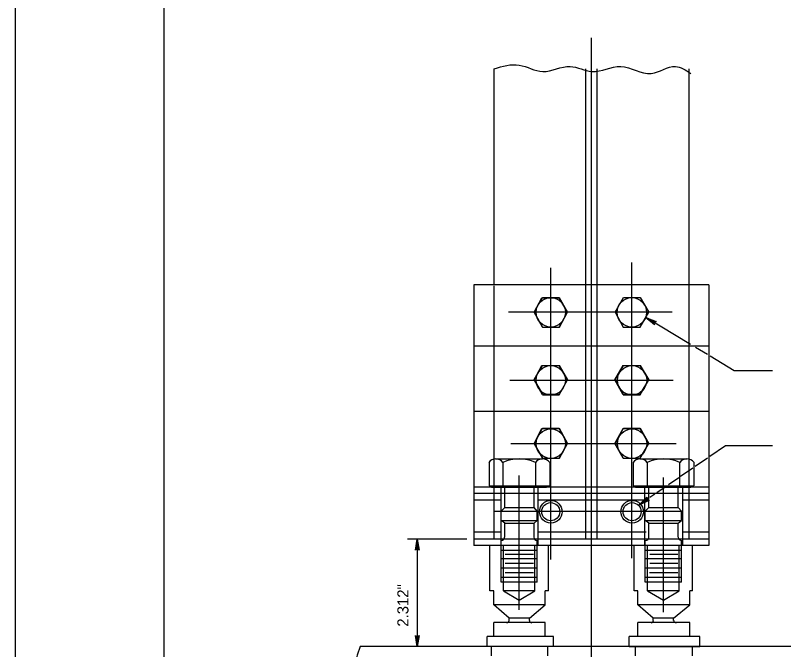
# Model space of a CAD drawing. Extents: x 637580 to 641008, y 294594 to 295782.
# Drawn here: x 637580.3 to 637787.5, y 294775.6 to 294946.5 of the extents above; entities that cross this region are included whole.
import ezdxf

# ---------------------------------------------------------------- set-up
doc = ezdxf.new("R2010")
doc.units = 0
for name, color, linetype in [('1', 7, 'Continuous'), ('2', 7, 'Continuous'), ('3', 7, 'Continuous'), ('PLT-BNDY', 7, 'Continuous')]:
    doc.layers.add(name, color=color, linetype=linetype)

# ---------------------------------------------------------------- blocks, each defined once
blk = doc.blocks.new('RARROW')
at = {"layer": '3'}
blk.add_lwpolyline([(-2.2695, 0.285), (-2.184875, 0.12075), (0, 0), (-2.2695, 0.285), (-2.38575, 0.384625), (0, 0), (-2.183125, -0.108), (-2.262875, -0.2705), (0, 0), (-2.38575, -0.379125), (-2.262875, -0.2705)], dxfattribs=at)

msp = doc.modelspace()

# ---------------------------------------------------------------- linework, layer by layer
at = {"layer": '1'}
msp.add_line((637620.31, 295172.63), (637620.31, 294608.63), dxfattribs=at)
at = {"layer": '2'}
for p, q in [((637735.69, 294688.38), (637735.69, 294940.5)), ((637709.44, 294873.88), (637709.44, 294932.13)), ((637734.19, 294805.38), (637734.19, 294932.13)), ((637737.19, 294805.38), (637737.19, 294932.13)), ((637762.06, 294873.63), (637762.06, 294932.13)), ((637746.56, 294800.25), (637746.56, 294879.88)), ((637724.69, 294799.88), (637724.69, 294878.5)), ((637767.31, 294873.88), (637703.94, 294873.88)), ((637703.94, 294873.88), (637703.94, 294805.38)), ((637709.44, 294805.38), (637709.44, 294873.63)), ((637762.06, 294857.96), (637762.06, 294873.63)), ((637767.31, 294873.88), (637767.31, 294805.38)), ((637720.19, 294866.5), (637722.44, 294870.5)), ((637720.19, 294866.5), (637722.31, 294870.38)), ((637722.31, 294870.38), (637726.94, 294870.38)), ((637722.44, 294870.5), (637726.94, 294870.5)), ((637726.94, 294870.5), (637729.19, 294866.5)), ((637729.19, 294866.5), (637726.94, 294870.38)), ((637742.06, 294866.5), (637744.31, 294870.5)), ((637744.31, 294870.5), (637748.81, 294870.5)), ((637748.81, 294870.5), (637751.19, 294866.5)), ((637757.44, 294866.5), (637713.31, 294866.5)), ((637720.19, 294866.5), (637722.44, 294862.5)), ((637722.44, 294862.5), (637720.19, 294866.5)), ((637724.69, 294866.5), (637724.69, 294866.5)), ((637724.69, 294866.5), (637724.69, 294866.5)), ((637724.69, 294866.5), (637724.69, 294866.5)), ((637726.94, 294862.5), (637729.19, 294866.5)), ((637727.06, 294862.5), (637729.19, 294866.5)), ((637742.06, 294866.5), (637744.19, 294862.5)), ((637746.56, 294866.5), (637746.56, 294866.5)), ((637746.56, 294866.5), (637746.56, 294866.5)), ((637746.56, 294866.5), (637746.56, 294866.5)), ((637748.81, 294862.5), (637751.19, 294866.5)), ((637748.81, 294862.5), (637751.19, 294866.5)), ((637762.39, 294857.83), (637750.33, 294865.06)), ((637722.44, 294862.5), (637727.06, 294862.5)), ((637722.44, 294862.5), (637726.94, 294862.5)), ((637744.19, 294862.5), (637748.81, 294862.5)), ((637767.31, 294857.38), (637703.94, 294857.38)), ((637762.06, 294805.38), (637762.06, 294857.89)), ((637766.96, 294855.09), (637763.72, 294857.03)), ((637774.19, 294850.75), (637767.71, 294854.64)), ((637720.19, 294848.25), (637722.44, 294852.13)), ((637720.19, 294848.25), (637722.31, 294852.13)), ((637722.31, 294852.13), (637726.94, 294852.13)), ((637722.44, 294852.13), (637726.94, 294852.13)), ((637726.94, 294852.13), (637729.19, 294848.25)), ((637729.19, 294848.25), (637726.94, 294852.13)), ((637741.94, 294848.25), (637744.19, 294852.13)), ((637742.06, 294848.25), (637744.31, 294852.13)), ((637744.19, 294852.13), (637748.81, 294852.13)), ((637744.31, 294852.13), (637748.81, 294852.13)), ((637748.81, 294852.13), (637751.19, 294848.25)), ((637751.19, 294848.25), (637748.81, 294852.13)), ((637784.46, 294850.75), (637774.19, 294850.75)), ((637757.69, 294848.13), (637713.69, 294848.13)), ((637720.19, 294848.25), (637722.44, 294844.38)), ((637722.44, 294844.25), (637720.19, 294848.25)), ((637724.69, 294848.13), (637724.69, 294848.13)), ((637724.69, 294848.13), (637724.69, 294848.13)), ((637724.69, 294848.13), (637724.69, 294848.13)), ((637726.94, 294844.25), (637729.19, 294848.25)), ((637727.06, 294844.38), (637729.19, 294848.25)), ((637744.19, 294844.25), (637741.94, 294848.25)), ((637742.06, 294848.25), (637744.19, 294844.38)), ((637746.56, 294848.13), (637746.56, 294848.13)), ((637746.56, 294848.13), (637746.56, 294848.13)), ((637746.56, 294848.13), (637746.56, 294848.13)), ((637748.81, 294844.38), (637751.19, 294848.25)), ((637748.81, 294844.25), (637751.19, 294848.25)), ((637722.44, 294844.38), (637727.06, 294844.38)), ((637722.44, 294844.25), (637726.94, 294844.25)), ((637744.19, 294844.38), (637748.81, 294844.38)), ((637744.19, 294844.25), (637748.81, 294844.25)), ((637767.31, 294839.75), (637703.94, 294839.75)), ((637720.19, 294831), (637722.44, 294835.25)), ((637720.19, 294831.13), (637722.31, 294835.13)), ((637722.31, 294835.13), (637726.94, 294835.13)), ((637722.44, 294835.25), (637726.94, 294835.25)), ((637726.94, 294835.25), (637729.19, 294831.13)), ((637729.19, 294831.13), (637726.94, 294835.13)), ((637741.94, 294831.13), (637744.19, 294835.13)), ((637742.06, 294831), (637744.31, 294835.25)), ((637744.19, 294835.13), (637748.81, 294835.13)), ((637744.31, 294835.25), (637748.81, 294835.25)), ((637748.81, 294835.25), (637751.19, 294831.13)), ((637751.19, 294831.13), (637748.81, 294835.13)), ((637758.56, 294831), (637713.94, 294831)), ((637722.44, 294827.13), (637720.19, 294831.13)), ((637720.19, 294831), (637722.44, 294827.13)), ((637724.69, 294831), (637724.69, 294831)), ((637724.69, 294831), (637724.69, 294831)), ((637724.69, 294831), (637724.69, 294831)), ((637726.94, 294827.13), (637729.19, 294831.13)), ((637727.06, 294827.13), (637729.19, 294831.13)), ((637744.19, 294827.13), (637741.94, 294831.13)), ((637742.06, 294831), (637744.19, 294827.13)), ((637746.56, 294831), (637746.56, 294831)), ((637746.56, 294831), (637746.56, 294831)), ((637746.56, 294831), (637746.56, 294831)), ((637748.81, 294827.13), (637751.19, 294831.13)), ((637748.81, 294827.13), (637751.19, 294831.13)), ((637771.79, 294830.51), (637767.61, 294827.65)), ((637784.46, 294830.51), (637771.79, 294830.51)), ((637708.06, 294826.13), (637708.06, 294826.13)), ((637708.06, 294826.13), (637708.06, 294819.75)), ((637709.81, 294827), (637709.81, 294827)), ((637709.81, 294827), (637711.81, 294827)), ((637711.81, 294827), (637720.56, 294827)), ((637711.81, 294826.13), (637711.81, 294819.75)), ((637711.81, 294826.13), (637711.81, 294826.13)), ((637716.19, 294827), (637716.19, 294827)), ((637720.56, 294827), (637722.44, 294827)), ((637720.56, 294826.13), (637720.56, 294819.75)), ((637720.56, 294826.13), (637720.56, 294826.13)), ((637722.44, 294827.13), (637727.06, 294827.13)), ((637722.44, 294827.13), (637726.94, 294827.13)), ((637722.44, 294827), (637722.44, 294827)), ((637724.44, 294826.13), (637724.44, 294826.13)), ((637724.44, 294826.13), (637724.44, 294819.75)), ((637744.19, 294827.13), (637748.81, 294827.13)), ((637744.19, 294827.13), (637748.81, 294827.13)), ((637746.94, 294826.13), (637746.94, 294826.13)), ((637746.94, 294826.13), (637746.94, 294819.75)), ((637748.69, 294827), (637748.69, 294827)), ((637748.69, 294827), (637750.69, 294827)), ((637750.69, 294827), (637759.44, 294827)), ((637750.69, 294826.13), (637750.69, 294819.75)), ((637750.69, 294826.13), (637750.69, 294826.13)), ((637755.06, 294827), (637755.06, 294827)), ((637759.44, 294827), (637761.44, 294827)), ((637759.44, 294826.13), (637759.44, 294819.75)), ((637759.44, 294826.13), (637759.44, 294826.13)), ((637761.44, 294827), (637761.44, 294827)), ((637763.31, 294826.13), (637763.31, 294826.13)), ((637763.31, 294826.13), (637763.31, 294819.75)), ((637766.98, 294827.21), (637763.65, 294824.94)), ((637763, 294824.48), (637759.65, 294822.19)), ((637716.19, 294786.25), (637716.19, 294822.5)), ((637755.06, 294785.63), (637755.06, 294822)), ((637759.23, 294821.9), (637756.44, 294819.99)), ((637708.06, 294819.75), (637724.44, 294819.75)), ((637708.69, 294819.38), (637708.56, 294819.75)), ((637712.31, 294813.88), (637712.31, 294819.75)), ((637720.19, 294813.88), (637720.19, 294819.75)), ((637723.56, 294819.38), (637723.56, 294819.75)), ((637746.94, 294819.75), (637763.31, 294819.75)), ((637747.56, 294819.38), (637747.44, 294819.75)), ((637751.19, 294813.88), (637751.19, 294819.75)), ((637759.06, 294813.88), (637759.06, 294819.75)), ((637762.44, 294819.38), (637762.56, 294819.75)), ((637711.44, 294819.38), (637703.94, 294819.38)), ((637767.31, 294817.63), (637703.94, 294817.63)), ((637708.69, 294819.38), (637723.56, 294819.38)), ((637711.19, 294819.38), (637711.19, 294803.63)), ((637716.19, 294819.38), (637716.19, 294819.38)), ((637716.19, 294819.38), (637716.19, 294819.38)), ((637721.31, 294803.63), (637721.31, 294819.38)), ((637750.44, 294819.38), (637721.31, 294819.38)), ((637747.56, 294819.38), (637762.44, 294819.38)), ((637749.94, 294819.38), (637749.94, 294803.5)), ((637752.75, 294817.46), (637751.4, 294816.53)), ((637755.24, 294819.16), (637753.29, 294817.83)), ((637755.06, 294819.38), (637755.06, 294819.38)), ((637755.06, 294819.38), (637755.06, 294819.38)), ((637767.31, 294819.38), (637760.19, 294819.38)), ((637760.31, 294803.63), (637760.31, 294819.38)), ((637711.44, 294815.88), (637703.94, 294815.88)), ((637749.94, 294815.88), (637721.31, 294815.88)), ((637751.01, 294816.27), (637748.44, 294814.5)), ((637767.31, 294815.88), (637760.19, 294815.88)), ((637711.31, 294812.88), (637712.31, 294813.88)), ((637712.31, 294813.88), (637720.19, 294813.88)), ((637721.06, 294812.88), (637720.19, 294813.88)), ((637750.19, 294812.88), (637751.19, 294813.88)), ((637751.19, 294813.88), (637759.06, 294813.88)), ((637759.94, 294812.88), (637759.06, 294813.88)), ((637709.31, 294812.88), (637758.06, 294812.88)), ((637711.31, 294812.88), (637721.06, 294812.88)), ((637711.31, 294810.38), (637711.31, 294812.88)), ((637716.19, 294812.88), (637716.19, 294812.88)), ((637721.06, 294810.38), (637721.06, 294812.88)), ((637724.69, 294812.88), (637724.69, 294812.88)), ((637746.56, 294812.88), (637746.56, 294812.88)), ((637750.19, 294812.88), (637759.94, 294812.88)), ((637750.19, 294810.38), (637750.19, 294812.88)), ((637755.06, 294812.88), (637755.06, 294812.88)), ((637759.94, 294810.38), (637759.94, 294812.88)), ((637711.31, 294810.38), (637721.06, 294810.38)), ((637712.31, 294809.63), (637711.31, 294810.38)), ((637712.31, 294805.88), (637712.31, 294809.63)), ((637712.31, 294809.63), (637720.19, 294809.63)), ((637720.19, 294809.63), (637721.06, 294810.38)), ((637720.19, 294805.88), (637720.19, 294809.63)), ((637750.19, 294810.38), (637759.94, 294810.38)), ((637751.19, 294809.63), (637750.19, 294810.38)), ((637751.19, 294805.88), (637751.19, 294809.63)), ((637751.19, 294809.63), (637759.06, 294809.63)), ((637759.06, 294809.63), (637759.94, 294810.38)), ((637759.06, 294805.88), (637759.06, 294809.63)), ((637711.44, 294807.25), (637703.94, 294807.25)), ((637750.44, 294807.25), (637721.31, 294807.25)), ((637767.31, 294807.25), (637760.19, 294807.25)), ((637702.06, 294805.38), (637686.06, 294805.38)), ((637688.69, 294805.38), (637688.69, 294776.38)), ((637703.94, 294805.38), (637703.94, 294803.63)), ((637767.31, 294805.38), (637703.94, 294805.38)), ((637735.69, 294805.38), (637735.69, 294805.38)), ((637767.31, 294805.38), (637767.31, 294803.63)), ((637767.31, 294803.63), (637703.94, 294803.63)), ((637709.94, 294803.63), (637704.56, 294803.63)), ((637708.31, 294791.38), (637708.31, 294803.63)), ((637711.31, 294803.63), (637710.44, 294803.63)), ((637711.31, 294793.75), (637711.31, 294805)), ((637711.94, 294791.38), (637711.94, 294803.63)), ((637716.19, 294803.63), (637716.19, 294803.63)), ((637716.19, 294803.63), (637716.19, 294803.63)), ((637720.44, 294791.38), (637720.44, 294803.63)), ((637721.06, 294793.75), (637721.06, 294805)), ((637724.06, 294791.38), (637724.06, 294803.63)), ((637735.69, 294803.63), (637735.69, 294803.63)), ((637735.69, 294803.63), (637735.69, 294803.63)), ((637747.19, 294791.38), (637747.19, 294803.63)), ((637750.19, 294793.75), (637750.19, 294805)), ((637750.81, 294791.38), (637750.81, 294803.63)), ((637755.06, 294803.63), (637755.06, 294803.63)), ((637755.06, 294803.63), (637755.06, 294803.63)), ((637759.31, 294791.38), (637759.31, 294803.63)), ((637759.94, 294793.75), (637759.94, 294805)), ((637762.94, 294791.38), (637762.94, 294803.63)), ((637711.31, 294802.38), (637721.06, 294802.38)), ((637712.44, 294801.25), (637720.06, 294801.25)), ((637750.19, 294802.38), (637759.94, 294802.38)), ((637751.44, 294801.25), (637758.94, 294801.25)), ((637711.31, 294800.13), (637721.06, 294800.13)), ((637712.44, 294798.88), (637720.06, 294798.88)), ((637750.19, 294800.13), (637759.94, 294800.13)), ((637751.44, 294798.88), (637758.94, 294798.88)), ((637711.31, 294797.63), (637721.06, 294797.63)), ((637750.19, 294797.63), (637759.94, 294797.63)), ((637711.31, 294795.13), (637721.06, 294795.13)), ((637712.44, 294796.38), (637720.06, 294796.38)), ((637716.19, 294795.13), (637716.19, 294795.13)), ((637750.19, 294795.13), (637759.94, 294795.13)), ((637751.31, 294796.38), (637758.94, 294796.38)), ((637755.06, 294795.13), (637755.06, 294795.13)), ((637721.06, 294793.75), (637711.31, 294793.75)), ((637759.94, 294793.75), (637750.19, 294793.75)), ((637709.31, 294791.38), (637708.31, 294791.38)), ((637709.31, 294787.63), (637709.31, 294791.38)), ((637720.44, 294791.38), (637711.94, 294791.38)), ((637711.94, 294791.38), (637716.19, 294788.88)), ((637716.19, 294788.88), (637720.44, 294791.38)), ((637723.19, 294787.63), (637723.19, 294791.38)), ((637724.06, 294791.38), (637723.19, 294791.38)), ((637748.19, 294791.38), (637747.19, 294791.38)), ((637748.19, 294787.63), (637748.19, 294791.38)), ((637759.31, 294791.38), (637750.81, 294791.38)), ((637750.81, 294791.38), (637755.06, 294788.88)), ((637755.06, 294788.88), (637759.31, 294791.38)), ((637762.19, 294787.63), (637762.19, 294791.38)), ((637762.94, 294791.38), (637762.19, 294791.38)), ((637716.19, 294788.88), (637716.19, 294788.88)), ((637755.06, 294788.88), (637755.06, 294788.88)), ((637713.44, 294784), (637709.31, 294787.63)), ((637723.19, 294787.63), (637709.31, 294787.63)), ((637718.94, 294784), (637723.19, 294787.63)), ((637752.31, 294784), (637748.19, 294787.63)), ((637762.19, 294787.63), (637748.19, 294787.63)), ((637757.81, 294784), (637762.19, 294787.63)), ((637709.31, 294779.13), (637709.31, 294782.88)), ((637723.19, 294782.88), (637709.31, 294782.88)), ((637713.44, 294783.38), (637713.44, 294784)), ((637718.94, 294784), (637713.44, 294784)), ((637718.94, 294783.38), (637718.94, 294784)), ((637723.19, 294779.13), (637723.19, 294782.88)), ((637748.19, 294779.13), (637748.19, 294782.88)), ((637762.19, 294782.88), (637748.19, 294782.88)), ((637752.31, 294783.38), (637752.31, 294784)), ((637757.81, 294784), (637752.31, 294784)), ((637757.81, 294783.38), (637757.81, 294784)), ((637762.19, 294779.13), (637762.19, 294782.88)), ((637725.44, 294779.13), (637707.56, 294779.13)), ((637707.56, 294776.5), (637707.56, 294779.13)), ((637716.19, 294779.13), (637716.19, 294779.13)), ((637725.44, 294776.5), (637725.44, 294779.13)), ((637764.94, 294779.13), (637745.81, 294779.13)), ((637745.81, 294776.38), (637745.81, 294779.13)), ((637755.06, 294779.13), (637755.06, 294779.13)), ((637764.94, 294776.38), (637764.94, 294779.13)), ((637794.44, 294776.38), (637673.31, 294776.38)), ((637707.56, 294776.5), (637725.44, 294776.5)), ((637708.69, 294773.88), (637708.69, 294776.5)), ((637723.81, 294776.5), (637723.81, 294773.88)), ((637745.81, 294776.38), (637764.94, 294776.38)), ((637747.56, 294773.88), (637747.56, 294776.38)), ((637762.81, 294776.38), (637762.81, 294773.88))]:
    msp.add_line(p, q, dxfattribs=at)
for centre, major_axis in [((637724.71, 294866.49), (0, 3.97)), ((637724.71, 294866.49), (0, -3.97)), ((637746.56, 294866.47), (0, 3.97)), ((637724.71, 294848.17), (0, 3.97)), ((637724.71, 294848.17), (0, -3.97)), ((637746.63, 294848.17), (0, 3.97)), ((637746.63, 294848.17), (0, -3.97)), ((637724.71, 294831.07), (0, 3.97)), ((637724.71, 294831.07), (0, -3.97)), ((637746.63, 294831.07), (0, 3.97)), ((637746.63, 294831.07), (0, -3.97)), ((637724.71, 294812.74), (0, 3.05)), ((637746.63, 294812.74), (0, 3.05)), ((637724.71, 294812.74), (0, 2.44)), ((637746.63, 294812.74), (0, 2.44))]:
    msp.add_ellipse(centre, major_axis=major_axis, ratio=0.996388, dxfattribs=at)
for centre, major_axis, start_param, end_param in [((637709.89, 294824.58), (0, -2.39), 2.218404, 4.064781), ((637716.18, 294816.23), (0, -10.74), 2.718335, 3.56485), ((637722.5, 294824.53), (0, -2.44), 2.228521, 4.054665), ((637748.82, 294824.58), (0, -2.39), 2.218404, 4.064781), ((637755.11, 294816.23), (0, -10.74), 2.718335, 3.56485), ((637761.43, 294824.53), (0, -2.44), 2.228521, 4.054665), ((637711.34, 294805.9), (0, 0.914), 3.141593, 4.712389), ((637721.07, 294805.9), (0, -0.914), 4.712389, 6.283185), ((637750.27, 294805.9), (0, 0.914), 3.141593, 4.712389), ((637760, 294805.9), (0, -0.914), 4.712389, 6.283185), ((637712.86, 294783.42), (0, 0.61), 3.141593, 4.712389), ((637719.55, 294783.42), (0, -0.61), 4.712389, 6.283185), ((637751.79, 294783.42), (0, 0.61), 3.141593, 4.712389), ((637758.48, 294783.42), (0, -0.61), 4.712389, 6.283185)]:
    msp.add_ellipse(centre, major_axis=major_axis, ratio=0.996388, start_param=start_param, end_param=end_param, dxfattribs=at)
for points in [[(637709.44, 294932.13), (637716.19, 294933.13), (637722.56, 294931.38), (637729.94, 294932.75), (637735.81, 294931.38), (637743.56, 294932.75), (637751.81, 294930.88), (637758.31, 294932.75), (637762.44, 294930.88)], [(637673.31, 294776.38), (637671.94, 294770.25), (637674.06, 294761.75), (637672.31, 294752.38), (637674.06, 294742.13), (637671.94, 294731.38), (637673.69, 294719.75), (637671.56, 294711.13), (637674.06, 294704.88), (637672.81, 294698.13)]]:
    msp.add_spline(points, degree=3, dxfattribs=at)
at = {"layer": 'PLT-BNDY'}
msp.add_lwpolyline([(637580.31, 295187.63), (638421.31, 295187.63), (638421.31, 294593.63), (637580.31, 294593.63)], close=True, dxfattribs=at)

# ---------------------------------------------------------------- block references
at = {"layer": '2'}
for p, xscale, yscale, rotation in [((637750.33, 294865.06), 1.2574347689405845, 1.3092961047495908, 149.40575640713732), ((637748.44, 294814.5), 1.2574347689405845, 1.3092961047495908, -145.39273517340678), ((637688.69, 294805.38), 1.2574347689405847, 1.3092961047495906, 89.99999999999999), ((637688.69, 294776.38), 1.2574347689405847, 1.3092961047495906, -90.00000000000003)]:
    msp.add_blockref('RARROW', p, dxfattribs=dict(at, xscale=xscale, yscale=yscale, rotation=rotation))

# ---------------------------------------------------------------- texts
at = {"layer": '1'}
msp.add_text('2.312"', height=3, rotation=90, dxfattribs=at).set_placement((637686.33, 294781.74))

doc.saveas('drawing.dxf')
